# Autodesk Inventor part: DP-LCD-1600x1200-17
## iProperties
Created: 2004-11
Part Number: DP-LCD-1600x1200-17
Cost Center: 0 lbmass
Document SubType Name: Modeling
Designer: busseym
Manufacturer: Standard
Standards Organization: Custom
Description: LCD MONITOR, 1600X1200
Stock Number: P-1832
Density: 1 g/cm^3
Dept. ID: Product Design
Description #2: ---
Finish #1: ---
Finish #2: ---
Material ID: ---
Project Number: ---
Author: busseym
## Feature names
1. Extrusion1
2. Extrusion2
3. Extrusion3
4. Revolution1
5. Extrusion4
6. Hole1
7. Rectangular Pattern1
8. Extrusion5
9. Extrusion6
10. Extrusion7
11. Extrusion8
12. Extrusion9
13. Extrusion10
14. Extrusion11
15. Hole3
16. Extrusion12
17. Hole4
18. USB BPort [Extrusion]
